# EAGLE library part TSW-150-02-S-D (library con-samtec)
THROUGH-HOLE .025" SQ POST HEADER Source: Samtec TSW.pdf
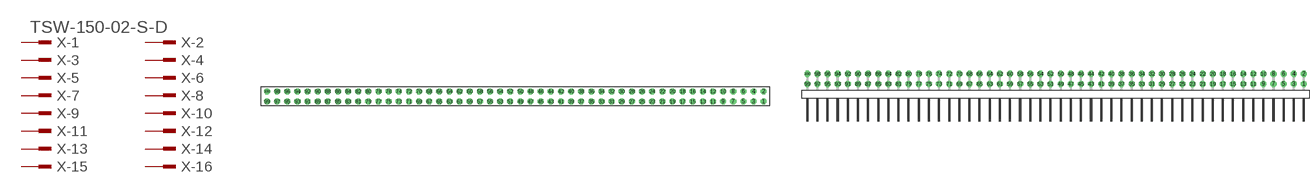
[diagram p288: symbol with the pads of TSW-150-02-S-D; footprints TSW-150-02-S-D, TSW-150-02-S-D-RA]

Designator prefix X; gates -1=MPINV -2=MPIN -3=MPIN -4=MPIN -5=MPIN -6=MPIN -7=MPIN -8=MPIN -9=MPIN -10=MPIN -11=MPIN -12=MPIN -13=MPIN -14=MPIN -15=MPIN -16=MPIN -17=MPIN -18=MPIN -19=MPIN -20=MPIN -21=MPIN -22=MPIN -23=MPIN -24=MPIN -25=MPIN -26=MPIN -27=MPIN -28=MPIN -29=MPIN -30=MPIN -31=MPIN -32=MPIN -33=MPIN -34=MPIN -35=MPIN -36=MPIN -37=MPIN -38=MPIN -39=MPIN -40=MPIN -41=MPIN -42=MPIN -43=MPIN -44=MPIN -45=MPIN -46=MPIN -47=MPIN -48=MPIN -49=MPIN -50=MPIN -51=MPIN -52=MPIN -53=MPIN -54=MPIN -55=MPIN -56=MPIN -57=MPIN -58=MPIN -59=MPIN -60=MPIN -61=MPIN -62=MPIN -63=MPIN -64=MPIN -65=MPIN -66=MPIN -67=MPIN -68=MPIN -69=MPIN -70=MPIN -71=MPIN -72=MPIN -73=MPIN -74=MPIN -75=MPIN -76=MPIN -77=MPIN -78=MPIN -79=MPIN -80=MPIN -81=MPIN -82=MPIN -83=MPIN -84=MPIN -85=MPIN -86=MPIN -87=MPIN -88=MPIN -89=MPIN -90=MPIN -91=MPIN -92=MPIN -93=MPIN -94=MPIN -95=MPIN -96=MPIN -97=MPIN -98=MPIN -99=MPIN -100=MPIN

## TSW-150-02-S-D (OC_FARNELL: unknown; OC_NEWARK: unknown)  [TSW-150-02-S-D]
1  -1:1  pas
2  -2:1  pas
3  -3:1  pas
4  -4:1  pas
5  -5:1  pas
6  -6:1  pas
7  -7:1  pas
8  -8:1  pas
9  -9:1  pas
10  -10:1  pas
11  -11:1  pas
12  -12:1  pas
13  -13:1  pas
14  -14:1  pas
15  -15:1  pas
16  -16:1  pas
17  -17:1  pas
18  -18:1  pas
19  -19:1  pas
20  -20:1  pas
21  -21:1  pas
22  -22:1  pas
23  -23:1  pas
24  -24:1  pas
25  -25:1  pas
26  -26:1  pas
27  -27:1  pas
28  -28:1  pas
29  -29:1  pas
30  -30:1  pas
31  -31:1  pas
32  -32:1  pas
33  -33:1  pas
34  -34:1  pas
35  -35:1  pas
36  -36:1  pas
37  -37:1  pas
38  -38:1  pas
39  -39:1  pas
40  -40:1  pas
41  -41:1  pas
42  -42:1  pas
43  -43:1  pas
44  -44:1  pas
45  -45:1  pas
46  -46:1  pas
47  -47:1  pas
48  -48:1  pas
49  -49:1  pas
50  -50:1  pas
51  -51:1  pas
52  -52:1  pas
53  -53:1  pas
54  -54:1  pas
55  -55:1  pas
56  -56:1  pas
57  -57:1  pas
58  -58:1  pas
59  -59:1  pas
60  -60:1  pas
61  -61:1  pas
62  -62:1  pas
63  -63:1  pas
64  -64:1  pas
65  -65:1  pas
66  -66:1  pas
67  -67:1  pas
68  -68:1  pas
69  -69:1  pas
70  -70:1  pas
71  -71:1  pas
72  -72:1  pas
73  -73:1  pas
74  -74:1  pas
75  -75:1  pas
76  -76:1  pas
77  -77:1  pas
78  -78:1  pas
79  -79:1  pas
80  -80:1  pas
81  -81:1  pas
82  -82:1  pas
83  -83:1  pas
84  -84:1  pas
85  -85:1  pas
86  -86:1  pas
87  -87:1  pas
88  -88:1  pas
89  -89:1  pas
90  -90:1  pas
91  -91:1  pas
92  -92:1  pas
93  -93:1  pas
94  -94:1  pas
95  -95:1  pas
96  -96:1  pas
97  -97:1  pas
98  -98:1  pas
99  -99:1  pas
100  -100:1  pas

## TSW-150-02-S-D-RA (OC_FARNELL: unknown; OC_NEWARK: unknown)  [TSW-150-02-S-D-RA]
Pads as for TSW-150-02-S-D

## Footprint TSW-150-02-S-D (pad centres in mm)
THROUGH-HOLE .025" SQ POST HEADER Source: Samtec TSW.pdf
drill 1 pad 1.5 octagon: 1 62.23,-1.27; 2 62.23,1.27; 3 59.69,-1.27; 4 59.69,1.27; 5 57.15,-1.27; 6 57.15,1.27; 7 54.61,-1.27; 8 54.61,1.27; 9 52.07,-1.27; 10 52.07,1.27; 11 49.53,-1.27; 12 49.53,1.27; 13 46.99,-1.27; 14 46.99,1.27; 15 44.45,-1.27; 16 44.45,1.27; 17 41.91,-1.27; 18 41.91,1.27; 19 39.37,-1.27; 20 39.37,1.27; 21 36.83,-1.27; 22 36.83,1.27; 23 34.29,-1.27; 24 34.29,1.27; 25 31.75,-1.27; 26 31.75,1.27; 27 29.21,-1.27; 28 29.21,1.27; 29 26.67,-1.27; 30 26.67,1.27; 31 24.13,-1.27; 32 24.13,1.27; 33 21.59,-1.27; 34 21.59,1.27; 35 19.05,-1.27; 36 19.05,1.27; 37 16.51,-1.27; 38 16.51,1.27; 39 13.97,-1.27; 40 13.97,1.27; 41 11.43,-1.27; 42 11.43,1.27; 43 8.89,-1.27; 44 8.89,1.27; 45 6.35,-1.27; 46 6.35,1.27; 47 3.81,-1.27; 48 3.81,1.27; 49 1.27,-1.27; 50 1.27,1.27; 51 -1.27,-1.27; 52 -1.27,1.27; 53 -3.81,-1.27; 54 -3.81,1.27; 55 -6.35,-1.27; 56 -6.35,1.27; 57 -8.89,-1.27; 58 -8.89,1.27; 59 -11.43,-1.27; 60 -11.43,1.27; 61 -13.97,-1.27; 62 -13.97,1.27; 63 -16.51,-1.27; 64 -16.51,1.27; 65 -19.05,-1.27; 66 -19.05,1.27; 67 -21.59,-1.27; 68 -21.59,1.27; 69 -24.13,-1.27; 70 -24.13,1.27; 71 -26.67,-1.27; 72 -26.67,1.27; 73 -29.21,-1.27; 74 -29.21,1.27; 75 -31.75,-1.27; 76 -31.75,1.27; 77 -34.29,-1.27; 78 -34.29,1.27; 79 -36.83,-1.27; 80 -36.83,1.27; 81 -39.37,-1.27; 82 -39.37,1.27; 83 -41.91,-1.27; 84 -41.91,1.27; 85 -44.45,-1.27; 86 -44.45,1.27; 87 -46.99,-1.27; 88 -46.99,1.27; 89 -49.53,-1.27; 90 -49.53,1.27; 91 -52.07,-1.27; 92 -52.07,1.27; 93 -54.61,-1.27; 94 -54.61,1.27; 95 -57.15,-1.27; 96 -57.15,1.27; 97 -59.69,-1.27; 98 -59.69,1.27; 99 -62.23,-1.27; 100 -62.23,1.27

## Footprint TSW-150-02-S-D-RA (pad centres in mm)
THROUGH-HOLE .025" SQ POST HEADER Source: Samtec TSW.pdf
drill 1 pad 1.5 octagon: 1 62.23,1.524; 2 62.23,4.064; 3 59.69,1.524; 4 59.69,4.064; 5 57.15,1.524; 6 57.15,4.064; 7 54.61,1.524; 8 54.61,4.064; 9 52.07,1.524; 10 52.07,4.064; 11 49.53,1.524; 12 49.53,4.064; 13 46.99,1.524; 14 46.99,4.064; 15 44.45,1.524; 16 44.45,4.064; 17 41.91,1.524; 18 41.91,4.064; 19 39.37,1.524; 20 39.37,4.064; 21 36.83,1.524; 22 36.83,4.064; 23 34.29,1.524; 24 34.29,4.064; 25 31.75,1.524; 26 31.75,4.064; 27 29.21,1.524; 28 29.21,4.064; 29 26.67,1.524; 30 26.67,4.064; 31 24.13,1.524; 32 24.13,4.064; 33 21.59,1.524; 34 21.59,4.064; 35 19.05,1.524; 36 19.05,4.064; 37 16.51,1.524; 38 16.51,4.064; 39 13.97,1.524; 40 13.97,4.064; 41 11.43,1.524; 42 11.43,4.064; 43 8.89,1.524; 44 8.89,4.064; 45 6.35,1.524; 46 6.35,4.064; 47 3.81,1.524; 48 3.81,4.064; 49 1.27,1.524; 50 1.27,4.064; 51 -1.27,1.524; 52 -1.27,4.064; 53 -3.81,1.524; 54 -3.81,4.064; 55 -6.35,1.524; 56 -6.35,4.064; 57 -8.89,1.524; 58 -8.89,4.064; 59 -11.43,1.524; 60 -11.43,4.064; 61 -13.97,1.524; 62 -13.97,4.064; 63 -16.51,1.524; 64 -16.51,4.064; 65 -19.05,1.524; 66 -19.05,4.064; 67 -21.59,1.524; 68 -21.59,4.064; 69 -24.13,1.524; 70 -24.13,4.064; 71 -26.67,1.524; 72 -26.67,4.064; 73 -29.21,1.524; 74 -29.21,4.064; 75 -31.75,1.524; 76 -31.75,4.064; 77 -34.29,1.524; 78 -34.29,4.064; 79 -36.83,1.524; 80 -36.83,4.064; 81 -39.37,1.524; 82 -39.37,4.064; 83 -41.91,1.524; 84 -41.91,4.064; 85 -44.45,1.524; 86 -44.45,4.064; 87 -46.99,1.524; 88 -46.99,4.064; 89 -49.53,1.524; 90 -49.53,4.064; 91 -52.07,1.524; 92 -52.07,4.064; 93 -54.61,1.524; 94 -54.61,4.064; 95 -57.15,1.524; 96 -57.15,4.064; 97 -59.69,1.524; 98 -59.69,4.064; 99 -62.23,1.524; 100 -62.23,4.064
